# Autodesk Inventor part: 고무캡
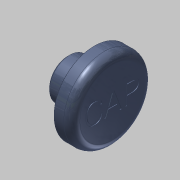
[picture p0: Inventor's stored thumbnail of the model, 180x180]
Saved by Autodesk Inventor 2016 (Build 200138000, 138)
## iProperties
Created: 2017-06
Part Number: 고무캡
Material: 고무
Document SubType Name: Modeling
Designer: mduedu
Density: 1 g/cm^3
Appearance: 고무 - 파란색 - 버전 1.1
Author: mduedu
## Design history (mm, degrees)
sketch "스케치1"
  geometry: L1 (0, 0)-(11, 0); L2 (11, 0)-(11, 10); L3 (11, 10)-(6.5, 10); L4 (0, 5)-(0, 0); L5 (0, 5)-(6, 5); L6 (6, 5)-(6, 9); L7 (6, 9)-(6.5, 9); L8 (6.5, 9)-(6.5, 10)
  constraints: 16 end point, 2 horizontal, 2 parallel, 2 perpendicular, 2 point on line, 1 vertical
  dimensions: "d0" = 20 diameter of L3 L1; "d2" = 10 diameter of L5 L1; "d6" = 5 distance between parallel lines of L2 L6; "d7" = 0.5 distance between parallel lines of L8 L6; "d8" = 18 diameter of L7 L1; "d9" = 6 distance between parallel lines of L6 L4
revolve "회전1" sketch "스케치1" stored, may be unused: angle "d10" = 90 deg
hole "구멍1" diameter "d22" = 7; stored, may be unused: countersink angle "d26" = 90 deg, drill point angle "d28" = 0 deg; dims "d23" = 6, "d24" = 4, "d25" = 2, "d27" = 6, "d32" = 10, "d33" = 10
chamfer "모따기1" distance "d13" = 0.5; stored, may be unused: second distance "d14" = 2, angle "d15" = 45 deg
fillet "모깎기3" dims "d29" = 1
fillet "모깎기1" dims "d16" = 0.1
fillet "모깎기2" dims "d17" = 2
sketch "스케치3"
  geometry: 2 further points
  constraints: 1 coincident, 1 other
feature "엠보싱1" sketch "스케치3" dims "d18" = 0.2, "d19" = 0
node "솔리드1"
